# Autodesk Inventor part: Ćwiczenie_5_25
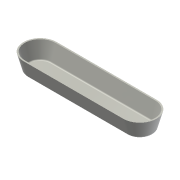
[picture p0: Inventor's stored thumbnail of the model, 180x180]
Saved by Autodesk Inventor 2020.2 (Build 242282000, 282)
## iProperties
Created: 2005-03
Part Number: Ćwiczenie_5_25
Document SubType Name: Modeling
Designer: F.Stasiak
Manufacturer: Standard
Standards Organization: Custom
Density: 1 g/cm^3
Material: Ogólny
Appearance: Gładkie — w kolorze kości słoniowej
Manager: www.cadconsulting.pl
Company: Fabian Stasiak CAD Consulting
Author: F.Stasiak
Subject: Zbiór ćwiczeń. Autodesk Inventor 2020. Kurs podstawowy
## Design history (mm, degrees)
sketch "Szkic1"
  geometry: L1 (-75, 25)-(75, 25); L2 (75, -25)-(-75, -25); L3 (0, 25)-(0, -25); A1 r 25 centre (75, 0) between (75, -25) and (75, 25); A2 r 25 centre (-75, 0) between (-75, 25) and (-75, -25); 2 further points
  constraints: 6 end point, 4 point on circle, 3 midpoint, 3 tangent, 2 centre point, 1 coincident, 1 horizontal, 1 parallel
  dimensions: "d0" = 200 dimension on A1 A2; "d1" = 50 distance between parallel lines of L1 L2
extrude "Wyciągnięcie proste1" new body sketch "Szkic1" distance "d2" = 25; taper "d3" = -15 deg
fillet "Zaokrąglenie1" dims "d4" = 4
feature "Skorupa1" dims "d5" = 2
node "Płaszczyzna konstrukcyjna1"
node "Bryła1"
node "Korpusy bryłowe"
node "Korpusy powierzchniowe"
other parameters: "d9" = -5
